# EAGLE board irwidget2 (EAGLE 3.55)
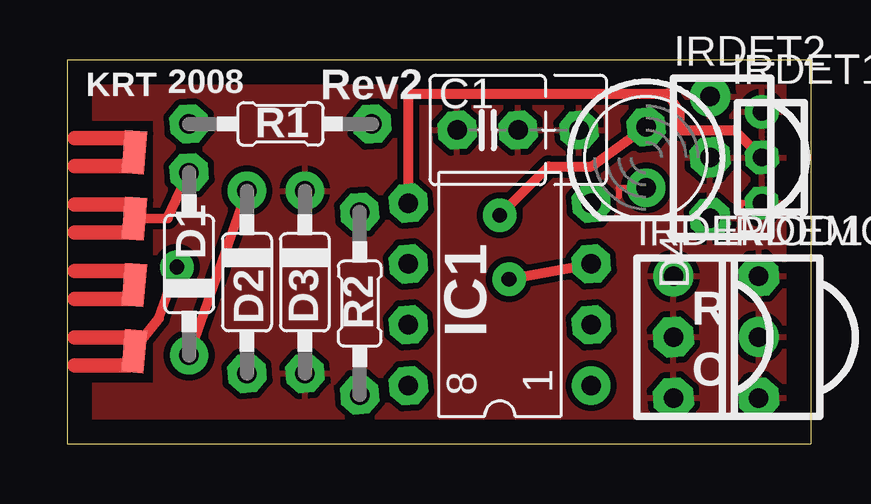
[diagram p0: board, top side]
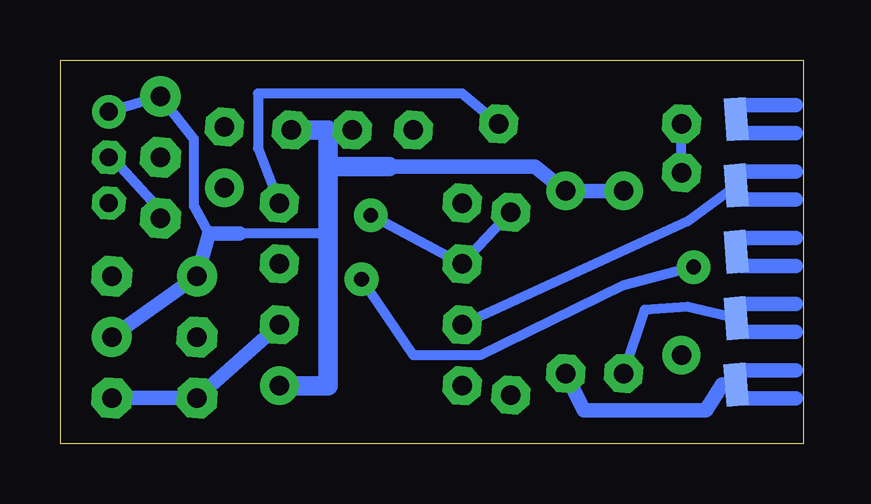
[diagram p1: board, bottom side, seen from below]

Size 30.99 x 16 mm. Coordinates in mm from the lower left corner, seen from the top.
Outline: 0,0 30.99,0 30.99,16 0,16 0,0
Copper layers used: Top, Bottom

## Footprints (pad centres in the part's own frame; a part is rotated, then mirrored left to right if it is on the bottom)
,5/5-5 = drill 0.813 pad 1.6 octagon:  -2.54,0;  2.54,0;  0,0
0 = drill 0.813 pad 1.6 octagon:  -5.08,0 | drill 0.813 pad 1.6 round:  2.54,0
D5 = drill 0.813 pad 1.6 octagon:  -1.27,0 | drill 0.813 pad 1.6 round:  1.27,0
L8 = drill 0.813 pad 1.6 round:  -3.81,-3.81 | drill 0.813 pad 1.6 octagon:  -1.27,-3.81;  1.27,-3.81;  3.81,-3.81;  3.81,3.81;  1.27,3.81;  -1.27,3.81;  -3.81,3.81
DM-OGP = drill 0.813 pad 1.676 octagon:  0,0;  0,-2.54 | drill 0.813 pad 1.676 round:  0,2.54
DM-OPG = drill 0.813 pad 1.676 round:  0,0 | drill 0.813 pad 1.676 octagon:  0,2.54;  0,-2.54
DET = drill 0.737 pad 1.397 round:  0,1.905 | drill 0.737 pad 1.397 octagon:  0,0;  0,-1.905
9PCBEG = smd 0.914 x 1.778 rotated 4.5:  -2.794,0 | smd 0.914 x 1.778 rotated 4.4:  -2.794,2.769 | smd 0.914 x 1.778 rotated 4.3:  -2.794,5.537 | smd 0.914 x 1.778 rotated 4.6:  -2.794,-2.769 | smd 0.914 x 1.778 rotated 4.7:  -2.794,-5.537 | smd 0.914 x 1.778 rotated 4.9 bottom:  -2.794,-1.384 | smd 0.914 x 1.778 rotated 4.8 bottom:  -2.794,1.384 | smd 0.914 x 1.778 rotated 4.7 bottom:  -2.794,4.153 | smd 0.914 x 1.778 rotated 5 bottom:  -2.794,-4.153
30 = drill 0.813 pad 1.6 octagon:  -5.08,0;  2.54,0

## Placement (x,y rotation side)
C1  2u2  [,5/5-5]  18.8,13.08 0 top
D1  1N4148  [0]  7.49,8 90 top
D2  1N4148  [0]  5.08,6.22 270 top
D3  1N5231  [0]  9.91,8 90 top
D4  IR LED  [D5]  24.13,11.94 270 top
IC1  12F629  [L8]  18.03,6.22 90 top
IRDEMOD1  OutGndVcc  [DM-OGP]  25.27,4.45 0 top
IRDEMOD2  OutVccGnd  [DM-OPG]  28.83,4.45 0 top
IRDET1  QSE15X  [DET]  28.96,11.94 0 top
IRDET2  TSOP98200  [DM-OGP]  26.8,11.94 0 top
J1  DE9F  [9PCBEG]  0,8 0 bottom
R1  10k  [30]  10.16,13.34 0 top
R2  2k2  [30]  12.19,7.11 90 top

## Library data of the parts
C1 = cap
D1-D3 = my_diode
D4 = led
IC1 = pic
IRDEMOD1 IRDEMOD2 IRDET1 IRDET2 = my_ir_mo
J1 = my_conn
R1 = myresist
R2 = my_resis

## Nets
DTR: D1. J1.
GND: C1. D3. D4. IC1. IRDEMOD1. IRDEMOD2. IRDET1. IRDET2. J1. R2.
N$1: C1. D1. D2. D3. IC1. IRDEMOD1. IRDEMOD2. IRDET1. IRDET2.
N$2: IC1. IRDET1. IRDET2.
N$3: IC1. IRDEMOD1. IRDEMOD2.
N$5: D4. IC1. R2.
N$21: IC1. R1.
RI: IC1. J1.
RTS: D2. J1. R1.
RXD: IC1. J1.

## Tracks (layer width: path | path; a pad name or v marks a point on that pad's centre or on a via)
DTR
  Bottom 0.406: 2.79,5.23 4.83,5.71 6.6,5.59 7.49,2.92
GND
  Top 0.254: 28.07,9.4 28.07,10.03 IRDET1. | 22.99,10.29 22.99,10.67 D4.
  Bottom 0.61: 2.79,2.46 3.38,2.46 4.06,1.4 9.14,1.4 9.91,2.92
  pour Top (isolate 0.254): 0.13,0.13 30.86,0.13 30.86,15.88 0.13,15.88 0.13,13.59 3.68,13.59 3.68,2.41 0.13,2.41
N$1
  Top 0.406: D2. D1.
  Bottom 0.406: 24.77,8.76 25.4,9.91 25.4,12.7 26.8,14.48 28.96,13.84 | 19.81,8.76 23.5,8.76
  Bottom 0.61: D1. D3. 11.18,11.56 17.27,11.56 | 23.5,8.76 24.77,8.76 25.27,6.99 28.83,4.45
  Bottom 0.813: 19.81,11.56 19.81,13.08 21.34,13.08 | 17.27,11.56 19.81,11.56 | 19.81,11.56 19.81,8.76 19.81,2.41 21.84,2.41
N$2
  Top 0.406: 14.22,10.03 14.22,14.61 25.02,14.61 25.53,13.84 25.53,13.08 27.81,13.08 28.96,11.94
  Bottom 0.305: 27.18,10.16 IRDET2.
  Bottom 0.406: 28.96,11.94 28.45,11.56 27.18,10.16
N$3
  Bottom 0.61: 21.84,4.95 IRDEMOD1. IRDEMOD2.
N$5  (via drill 0.61 pad 1.4)
  Top 0.406: 24.13,13.21 21.84,11.56 20.07,11.56 v18.03,9.53
  Bottom 0.406: R2. 14.22,7.49 v18.03,9.53
N$21
  Bottom 0.406: R1. 14.22,14.61 22.73,14.61 22.73,12.32 21.84,10.03
RI  (via drill 0.61 pad 1.4)
  Top 0.406: v18.41,6.86 21.84,7.49 | v4.57,7.37 3.81,5.21 2.79,3.94 J1.
  Bottom 0.406: v18.41,6.86 16.26,3.68 13.46,3.68 7.49,6.6 v4.57,7.37
RTS
  Top 0.406: 2.79,9.38 4.19,9.4 5.08,11.3
  Bottom 0.406: 5.08,11.3 5.08,13.34
RXD
  Bottom 0.406: 2.79,10.77 4.83,9.27 14.22,4.95

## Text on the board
tPlace: 2008 | KRT | Rev2 | R | C
_layer121: 2006 | KRT | 8 | 1
_layer125: R1 | C1 | D2 | D1 | D3 | IC1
